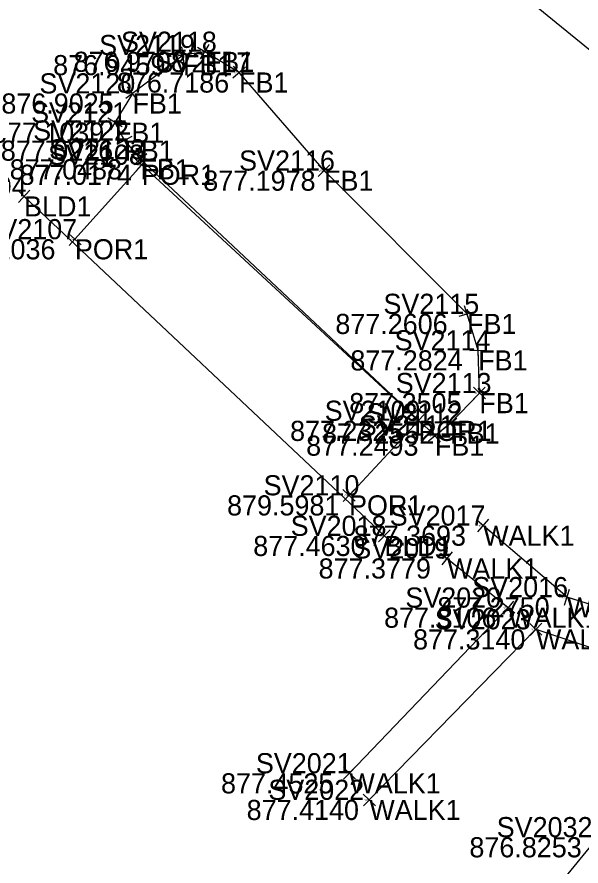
# Model space of a CAD drawing. Extents: x 1469677 to 1493262, y 375219 to 389293.
# Drawn here: x 1480082.9 to 1480116.5, y 379383.5 to 379434.1 of the extents above; entities that cross this region are included whole.
import ezdxf

# ---------------------------------------------------------------- set-up
doc = ezdxf.new("R2010")
doc.units = 0
for name, color, linetype in [('Border', 7, 'Continuous'), ('DV_X_Lot_Line', 7, 'Continuous'), ('DV_X_Text', 7, 'Continuous'), ('GK_Visualization', 7, 'Continuous'), ('PNTELEV', 7, 'Continuous'), ('RW_P_Esmt_SW', 7, 'Continuous'), ('text', 7, 'Continuous'), ('Text Property', 7, 'Continuous'), ('UT_X_Water', 7, 'Continuous')]:
    doc.layers.add(name, color=color, linetype=linetype)

msp = doc.modelspace()

# ---------------------------------------------------------------- linework, layer by layer
at = {"layer": 'Border'}
msp.add_lwpolyline([(1480104.802, 379403.171), (1480083.333, 379423.411)], dxfattribs=at)
at = {"layer": 'DV_X_Lot_Line'}
for points in [[(1480132.927, 379394.064), (1480131.678, 379394.217), (1480129.623, 379395.124), (1480129.685, 379395.088), (1480115.69, 379399.516), (1480110.694, 379403.782)], [(1480108.536, 379401.827), (1480112.184, 379398.894), (1480102.722, 379389.018)], [(1480103.907, 379387.432), (1480113.836, 379397.599), (1480128.867, 379392.608), (1480129.145, 379392.467), (1480129.878, 379392.11), (1480130.393, 379392.142), (1480130.835, 379391.865)]]:
    msp.add_lwpolyline(points, dxfattribs=at)
at = {"layer": 'PNTELEV'}
for p, q in [((1480092.878, 379431.339), (1480092.728, 379432.327)), ((1480094.531, 379431.773), (1480093.675, 379432.29)), ((1480093.844, 379431.604), (1480094.362, 379432.459)), ((1480093.297, 379431.909), (1480092.309, 379431.758)), ((1480092.803, 379431.833), (1480092.803, 379431.833)), ((1480094.103, 379432.032), (1480094.103, 379432.032)), ((1480095.767, 379430.469), (1480096.523, 379431.124)), ((1480096.472, 379430.419), (1480095.818, 379431.175)), ((1480096.145, 379430.797), (1480096.145, 379430.797)), ((1480090.19, 379429.85), (1480089.394, 379429.245)), ((1480090.094, 379429.149), (1480089.49, 379429.946)), ((1480089.792, 379429.547), (1480089.792, 379429.547)), ((1480089.001, 379428.235), (1480088.485, 379427.379)), ((1480089.171, 379427.549), (1480088.315, 379428.065)), ((1480088.743, 379427.807), (1480088.743, 379427.807)), ((1480089.073, 379427.18), (1480089.539, 379426.295)), ((1480089.748, 379426.97), (1480088.864, 379426.504)), ((1480089.306, 379426.737), (1480089.306, 379426.737)), ((1480090.648, 379425.947), (1480089.89, 379425.294)), ((1480089.943, 379425.999), (1480090.595, 379425.242)), ((1480089.97, 379425.63), (1480090.714, 379424.962)), ((1480090.008, 379424.924), (1480090.676, 379425.668)), ((1480090.269, 379425.62), (1480090.269, 379425.62)), ((1480090.342, 379425.296), (1480090.342, 379425.296)), ((1480100.854, 379424.593), (1480101.562, 379425.3)), ((1480101.561, 379424.593), (1480100.855, 379425.3)), ((1480101.208, 379424.947), (1480101.208, 379424.947)), ((1480083.697, 379423.068), (1480082.969, 379423.754)), ((1480082.99, 379423.047), (1480083.676, 379423.775)), ((1480083.333, 379423.411), (1480083.333, 379423.411)), ((1480085.987, 379421.19), (1480086.731, 379420.523)), ((1480086.025, 379420.484), (1480086.693, 379421.229)), ((1480086.359, 379420.856), (1480086.359, 379420.856)), ((1480109.254, 379416.26), (1480110.212, 379416.55)), ((1480109.878, 379415.926), (1480109.588, 379416.883)), ((1480109.733, 379416.405), (1480109.733, 379416.405)), ((1480110.407, 379413.73), (1480110.377, 379414.729)), ((1480109.892, 379414.215), (1480110.892, 379414.244)), ((1480110.392, 379414.23), (1480110.392, 379414.23)), ((1480110.106, 379412.031), (1480110.826, 379411.337)), ((1480110.119, 379411.324), (1480110.813, 379412.044)), ((1480110.466, 379411.684), (1480110.466, 379411.684)), ((1480106.461, 379410.37), (1480107.195, 379409.691)), ((1480107.168, 379410.397), (1480106.488, 379409.664)), ((1480106.828, 379410.03), (1480106.828, 379410.03)), ((1480108.333, 379409.563), (1480109.115, 379410.187)), ((1480108.412, 379410.266), (1480109.036, 379409.484)), ((1480108.724, 379409.875), (1480108.724, 379409.875)), ((1480107.424, 379408.838), (1480108.206, 379409.462)), ((1480107.503, 379409.541), (1480108.127, 379408.759)), ((1480107.815, 379409.15), (1480107.815, 379409.15)), ((1480103.063, 379405.246), (1480102.331, 379405.927)), ((1480103.037, 379405.953), (1480102.357, 379405.22)), ((1480102.697, 379405.586), (1480102.697, 379405.586)), ((1480111.074, 379403.457), (1480110.314, 379404.107)), ((1480110.369, 379403.402), (1480111.019, 379404.162)), ((1480110.694, 379403.782), (1480110.694, 379403.782)), ((1480105.166, 379402.828), (1480104.438, 379403.514)), ((1480104.459, 379402.807), (1480105.145, 379403.535)), ((1480104.802, 379403.171), (1480104.802, 379403.171)), ((1480108.146, 379402.14), (1480108.926, 379401.514)), ((1480108.849, 379402.217), (1480108.223, 379401.437)), ((1480108.536, 379401.827), (1480108.536, 379401.827)), ((1480115.539, 379399.039), (1480115.841, 379399.993)), ((1480112.497, 379399.284), (1480111.871, 379398.504)), ((1480116.167, 379399.365), (1480115.213, 379399.667)), ((1480115.69, 379399.516), (1480115.69, 379399.516)), ((1480111.794, 379399.207), (1480112.574, 379398.581)), ((1480112.184, 379398.894), (1480112.184, 379398.894)), ((1480113.478, 379397.948), (1480114.194, 379397.249)), ((1480113.487, 379397.241), (1480114.185, 379397.957)), ((1480113.836, 379397.599), (1480113.836, 379397.599)), ((1480103.083, 379388.672), (1480102.361, 379389.364)), ((1480103.068, 379389.379), (1480102.376, 379388.657)), ((1480102.722, 379389.018), (1480102.722, 379389.018)), ((1480103.549, 379387.782), (1480104.265, 379387.083)), ((1480103.558, 379387.075), (1480104.256, 379387.79)), ((1480103.907, 379387.432), (1480103.907, 379387.432))]:
    msp.add_line(p, q, dxfattribs=at)
at = {"layer": 'text'}
for points in [[(1480127.721, 379395.358), (1480131.799, 379398.039), (1480133.273, 379401.352), (1480135.459, 379407.36), (1480135.6, 379409.555), (1480135.793, 379413.076), (1480135.014, 379415.657), (1480133.026, 379417.684), (1480123.803, 379426.624), (1480113.121, 379435.343), (1480106.984, 379440.926), (1480103.73, 379443.918), (1480102.529, 379445.074), (1480100.774, 379445.951), (1480096.595, 379444.059), (1480092.174, 379441.029), (1480086.377, 379436.591)], [(1480102.555, 379367.391), (1480110.126, 379376.156), (1480117.553, 379385.207), (1480124.442, 379393.548)]]:
    msp.add_lwpolyline(points, dxfattribs=at)
at = {"layer": 'Text Property'}
msp.add_lwpolyline([(1480107.815, 379409.15), (1480108.724, 379409.875), (1480110.466, 379411.684), (1480110.392, 379414.23), (1480109.733, 379416.405), (1480101.208, 379424.947), (1480096.145, 379430.797), (1480094.103, 379432.032), (1480092.803, 379431.833), (1480089.792, 379429.547), (1480088.743, 379427.807), (1480089.306, 379426.737), (1480090.269, 379425.62)], close=True, dxfattribs=at)
at = {"layer": 'UT_X_Water'}
msp.add_lwpolyline([(1480086.359, 379420.856), (1480090.342, 379425.296), (1480106.828, 379410.03), (1480102.697, 379405.586)], dxfattribs=at)

# ---------------------------------------------------------------- texts
at = {"layer": 'DV_X_Text'}
for s, height, p in [('876.9459', 1.2, (1480085.065, 379430.633)), ('876.9708', 1.2, (1480086.28, 379430.832)), ('876.95', 0.06, (1480092.521, 379431.773)), ('876.97', 0.06, (1480093.821, 379431.972)), ('876.7186', 1.2, (1480088.861, 379429.597)), ('876.72', 0.06, (1480095.865, 379430.737)), ('876.9025', 1.2, (1480081.978, 379428.347)), ('876.90', 0.06, (1480089.505, 379429.487)), ('877.1039', 1.2, (1480081.412, 379426.607)), ('877.10', 0.06, (1480088.482, 379427.747)), ('877.0216', 1.2, (1480081.946, 379425.537)), ('877.02', 0.06, (1480089.022, 379426.677)), ('877.0488', 1.2, (1480082.474, 379424.42)), ('877.05', 0.06, (1480089.984, 379425.56)), ('877.0174', 1.2, (1480083.067, 379424.096)), ('877.02', 0.06, (1480090.058, 379425.236)), ('877.1978', 1.2, (1480094.009, 379423.747)), ('877.20', 0.06, (1480100.925, 379424.887)), ('877.04', 0.06, (1480083.644, 379422.79)), ('877.2036', 1.2, (1480078.508, 379419.656)), ('877.20', 0.06, (1480086.076, 379420.796)), ('877.2606', 1.2, (1480101.882, 379415.205)), ('877.26', 0.06, (1480109.451, 379416.345)), ('877.2824', 1.2, (1480102.777, 379413.03)), ('877.28', 0.06, (1480110.113, 379414.17)), ('877.2505', 1.2, (1480102.709, 379410.484)), ('877.25', 0.06, (1480110.188, 379411.624)), ('877.2325', 1.2, (1480099.184, 379408.83)), ('877.2552', 1.2, (1480101.09, 379408.675)), ('877.23', 0.06, (1480106.55, 379409.97)), ('877.26', 0.06, (1480108.442, 379409.815)), ('877.2493', 1.2, (1480100.143, 379407.95)), ('877.25', 0.06, (1480107.537, 379409.09)), ('879.5981', 1.2, (1480095.429, 379404.386)), ('879.60', 0.06, (1480102.41, 379405.526)), ('877.3693', 1.2, (1480102.975, 379402.582)), ('877.37', 0.06, (1480110.414, 379403.722)), ('877.4630', 1.2, (1480096.988, 379401.971)), ('877.46', 0.06, (1480104.519, 379403.111)), ('877.3779', 1.2, (1480100.883, 379400.627)), ('877.38', 0.06, (1480108.255, 379401.767)), ('877.2750', 1.2, (1480107.961, 379398.316)), ('877.27', 0.06, (1480115.412, 379399.456)), ('877.3106', 1.2, (1480104.787, 379397.694)), ('877.31', 0.06, (1480111.926, 379398.834)), ('877.3140', 1.2, (1480106.514, 379396.399)), ('877.31', 0.06, (1480113.578, 379397.539)), ('877.4525', 1.2, (1480095.069, 379387.818)), ('877.45', 0.06, (1480102.442, 379388.958)), ('877.4140', 1.2, (1480096.595, 379386.232)), ('877.41', 0.06, (1480103.65, 379387.372)), ('876.8253', 1.2, (1480109.872, 379384.007))]:
    msp.add_text(s, height=height, dxfattribs=at).set_placement(p)
at = {"layer": 'GK_Visualization'}
for s, p in [('FB1', (1480092.803, 379430.633)), ('FB1', (1480094.103, 379430.832)), ('FB1', (1480096.145, 379429.597)), ('FB1', (1480089.792, 379428.347)), ('FB1', (1480088.743, 379426.607)), ('FB1', (1480089.306, 379425.537)), ('FB1', (1480090.269, 379424.42)), ('POR1', (1480090.342, 379424.096)), ('FB1', (1480101.208, 379423.747)), ('BLD1', (1480083.333, 379422.211)), ('POR1', (1480086.359, 379419.656)), ('FB1', (1480109.733, 379415.205)), ('FB1', (1480110.392, 379413.03)), ('FB1', (1480110.466, 379410.484)), ('POR1', (1480106.828, 379408.83)), ('FB1', (1480108.724, 379408.675)), ('FB1', (1480107.815, 379407.95)), ('POR1', (1480102.697, 379404.386)), ('WALK1', (1480110.694, 379402.582)), ('BLD1', (1480104.802, 379401.971)), ('WALK1', (1480108.536, 379400.627)), ('WALK1', (1480115.69, 379398.316)), ('WALK1', (1480112.184, 379397.694)), ('WALK1', (1480113.836, 379396.399)), ('WALK1', (1480102.722, 379387.818)), ('WALK1', (1480103.907, 379386.232))]:
    msp.add_text(s, height=1.2, dxfattribs=at).set_placement(p)
at = {"layer": 'RW_P_Esmt_SW'}
for s, height, p in [('SV2118', 1.2, (1480089.106, 379432.032)), ('SV2119', 1.2, (1480087.806, 379431.833)), ('SV2117', 1.2, (1480091.158, 379430.797)), ('SV2119', 0.06, (1480092.553, 379431.833)), ('SV2118', 0.06, (1480093.853, 379432.032)), ('SV2120', 1.2, (1480084.247, 379429.547)), ('SV2117', 0.06, (1480095.896, 379430.797)), ('SV2120', 0.06, (1480089.515, 379429.547)), ('SV2121', 1.2, (1480083.753, 379427.807)), ('SV2122', 1.2, (1480083.874, 379426.737)), ('SV2121', 0.06, (1480088.493, 379427.807)), ('SV2123', 1.2, (1480084.828, 379425.62)), ('SV2122', 0.06, (1480089.034, 379426.737)), ('SV2108', 1.2, (1480084.759, 379425.296)), ('SV2116', 1.2, (1480096.145, 379424.947)), ('SV2123', 0.06, (1480089.997, 379425.62)), ('SV2108', 0.06, (1480090.063, 379425.296)), ('SV2104', 1.2, (1480077.769, 379423.411)), ('SV2116', 0.06, (1480100.955, 379424.947)), ('SV2104', 0.06, (1480083.65, 379422.85)), ('SV2107', 1.2, (1480080.785, 379420.856)), ('SV2107', 0.06, (1480086.08, 379420.856)), ('SV2115', 1.2, (1480104.746, 379416.405)), ('SV2115', 0.06, (1480109.484, 379416.405)), ('SV2114', 1.2, (1480105.414, 379414.23)), ('SV2114', 0.06, (1480110.143, 379414.23)), ('SV2113', 1.2, (1480105.479, 379411.684)), ('SV2113', 0.06, (1480110.217, 379411.684)), ('SV2109', 1.2, (1480101.245, 379410.03)), ('SV2112', 1.2, (1480103.746, 379409.875)), ('SV2111', 1.2, (1480103.279, 379409.15)), ('SV2109', 0.06, (1480106.549, 379410.03)), ('SV2112', 0.06, (1480108.475, 379409.875)), ('SV2111', 0.06, (1480107.588, 379409.15)), ('SV2110', 1.2, (1480097.606, 379405.586)), ('SV2110', 0.06, (1480102.442, 379405.586)), ('SV2017', 1.2, (1480105.12, 379403.782)), ('SV2018', 1.2, (1480099.219, 379403.171)), ('SV2017', 0.06, (1480110.415, 379403.782)), ('SV2019', 1.2, (1480102.953, 379401.827)), ('SV2018', 0.06, (1480104.523, 379403.171)), ('SV2019', 0.06, (1480108.257, 379401.827)), ('SV2016', 1.2, (1480110.041, 379399.516)), ('SV2020', 1.2, (1480106.052, 379398.894)), ('SV2016', 0.06, (1480115.408, 379399.516)), ('SV2023', 1.2, (1480107.808, 379397.599)), ('SV2020', 0.06, (1480111.877, 379398.894)), ('SV2023', 0.06, (1480113.535, 379397.599)), ('SV2021', 1.2, (1480097.145, 379389.018)), ('SV2022', 1.2, (1480097.889, 379387.432)), ('SV2021', 0.06, (1480102.443, 379389.018)), ('SV2022', 0.06, (1480103.606, 379387.432)), ('SV2032', 1.2, (1480111.497, 379385.207))]:
    msp.add_text(s, height=height, dxfattribs=at).set_placement(p)

doc.saveas('drawing.dxf')
